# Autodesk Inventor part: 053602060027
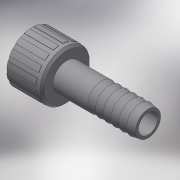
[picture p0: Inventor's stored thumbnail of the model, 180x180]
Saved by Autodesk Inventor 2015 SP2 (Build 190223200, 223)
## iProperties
Created: 2017-10
Part Number: 053602060027
Material: Generic
Description: PLASSON HOSE NOZZLE+NUT/THR. 2.3/4"-60
Document SubType Name: Modeling
Designer: KIM
Density: 1 g/cm^3
Appearance: Default
Author: KIM
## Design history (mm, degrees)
derived "053602.ipt"
feature "Solid1::053602.ipt"
tag "TaggingFeature1"
body "Solid1"
other parameters: "d0" = 118, "d1" = 170 deg, "d5" = 94.2912, "d6" = 42, "d8" = 47.2, "d9" = 78.576, "d10" = 35.4, "d11" = 21.24, "d12" = 29.5, "d13" = 92.71968, "d14" = 3.9288, "d17" = 7.8576, "d18" = 3.9288, "d19" = 33.04, "d20" = 0, "d22" = 360 deg, "d_" = 16, "H_" = 118, "G_" = 78.576
